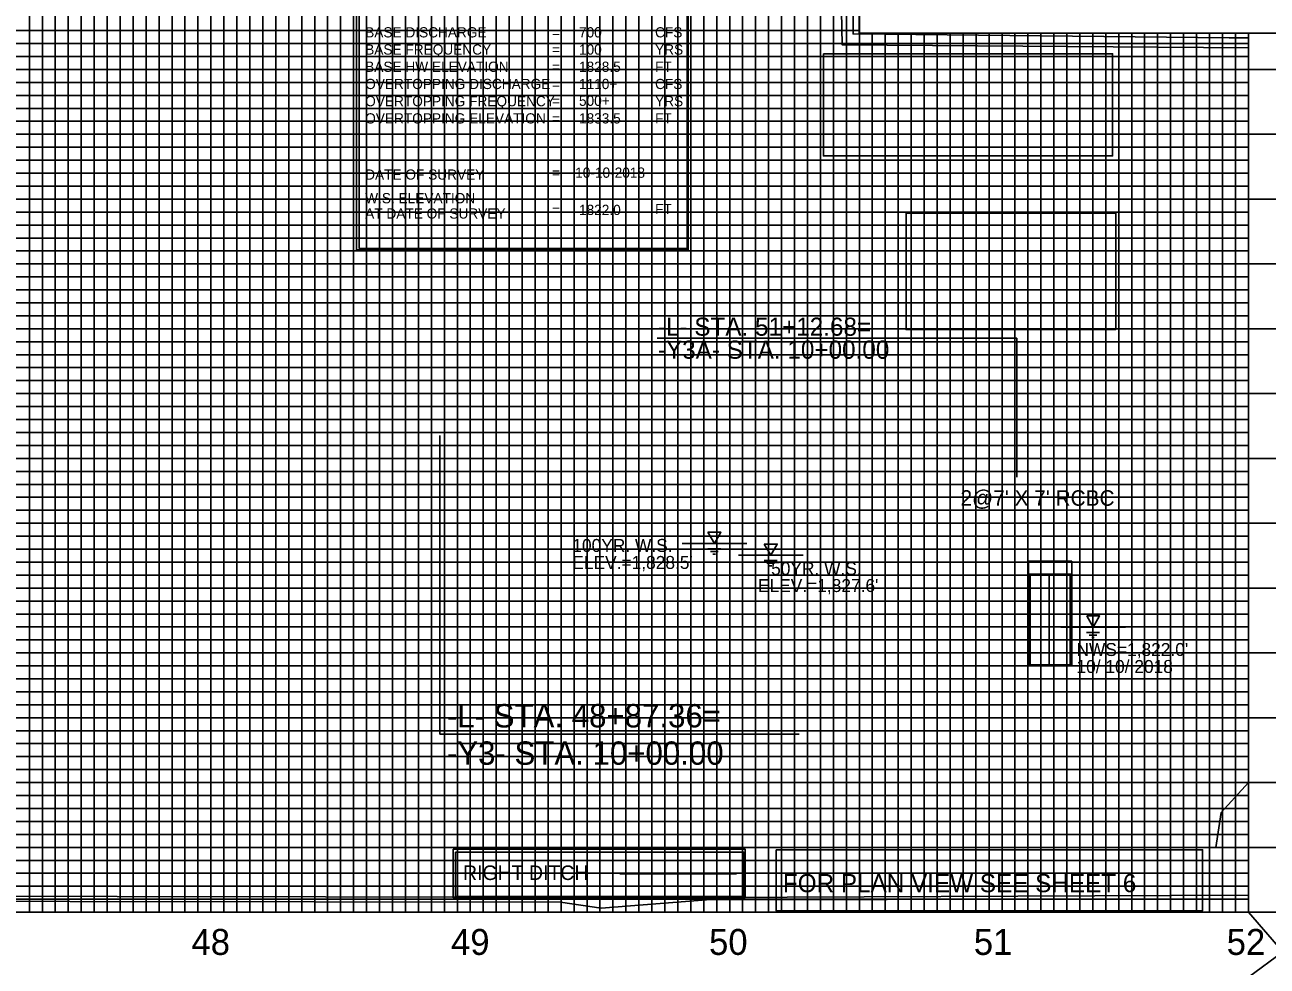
# Model space of a CAD drawing. Extents: x 557032 to 562069, y 513430 to 515874.
# Drawn here: x 558177.7 to 558656.7, y 515328.5 to 515691.5 of the extents above; entities that cross this region are included whole.
import ezdxf

# ---------------------------------------------------------------- set-up
doc = ezdxf.new("R2010")
doc.units = 0
for name, color, linetype in [('Default', 7, 'Continuous'), ('Exist Vertical Profile Horizontal Axis Label Major', 7, 'Continuous'), ('Prop Grid Mask', 7, 'Continuous'), ('Prop PFL Ditch Label CELL', 7, 'Continuous'), ('Prop Vertical Profile Curve Label', 7, 'Continuous'), ('Prop VPI Label', 7, 'Continuous'), ('Scratch_Level_5', 7, 'Continuous'), ('Sheet DOT Grid CELL', 7, 'Continuous'), ('Sheet Layout Profile Border Port 1', 7, 'Continuous'), ('Sheet Profile CELL', 7, 'Continuous'), ('Sheet Profile Grid Major CELL', 7, 'Continuous'), ('Sheet Profile Grid Middle CELL', 7, 'Continuous'), ('Sheet Profile Grid Minor CELL', 7, 'Continuous'), ('Sheet Sticker Exception Certification CELL', 7, 'Continuous')]:
    doc.layers.add(name, color=color, linetype=linetype)

msp = doc.modelspace()

# ---------------------------------------------------------------- linework, layer by layer
at = {"layer": 'Default'}
for p, q in [((558431.08, 515491.43), (558456.08, 515491.44)), ((558441, 515489.41), (558446, 515489.42)), ((558442, 515488.41), (558445, 515488.42)), ((558443, 515487.41), (558444, 515487.42)), ((558452.81, 515486.92), (558477.81, 515486.93)), ((558462.74, 515484.9), (558467.74, 515484.9)), ((558463.74, 515483.9), (558466.74, 515483.9)), ((558464.74, 515482.9), (558465.74, 515482.9)), ((558581.35, 515484.7), (558564.69, 515484.7)), ((558564.69, 515444.7), (558564.69, 515484.7)), ((558581.35, 515444.7), (558581.35, 515484.7)), ((558581.35, 515479.7), (558564.69, 515479.7)), ((558565.35, 515444.7), (558565.35, 515479.7)), ((558572.69, 515479.7), (558572.69, 515444.7)), ((558580.69, 515444.7), (558580.69, 515479.7)), ((558577.09, 515459.2), (558602.09, 515459.21)), ((558587.02, 515457.17), (558592.02, 515457.18)), ((558588.02, 515456.18), (558591.02, 515456.18)), ((558589.02, 515455.18), (558590.02, 515455.18)), ((558581.35, 515444.7), (558564.69, 515444.7))]:
    msp.add_line(p, q, dxfattribs=at)
for points in [[(558441.07, 515495.78), (558446.07, 515495.78), (558443.58, 515491.44)], [(558462.81, 515491.26), (558467.81, 515491.27), (558465.31, 515486.93)], [(558587.09, 515463.54), (558592.09, 515463.54), (558589.59, 515459.2)]]:
    msp.add_lwpolyline(points, close=True, dxfattribs=at)
at = {"layer": 'Prop Grid Mask'}
msp.add_lwpolyline([(558342.89, 515373.63), (558455.39, 515373.63), (558455.39, 515354.88), (558342.89, 515354.88)], close=True, dxfattribs=at)
at = {"layer": 'Prop PFL Ditch Label CELL'}
for p, q in [((558407.05, 515364.14), (558452.05, 515364.14)), ((558342.89, 515362.38), (558342.89, 515362.38))]:
    msp.add_line(p, q, dxfattribs=at)
at = {"layer": 'Prop Vertical Profile Curve Label'}
for points in [[(558305.55, 515740.01), (558433.43, 515740.01), (558433.43, 515604.72), (558305.55, 515604.72)], [(558485.58, 515680.31), (558597.1, 515680.31), (558597.1, 515640.93), (558485.58, 515640.93)], [(558517.44, 515618.88), (558598.31, 515618.88), (558598.31, 515573.96), (558517.44, 515573.96)]]:
    msp.add_lwpolyline(points, close=True, dxfattribs=at)
at = {"layer": 'Prop VPI Label'}
for p, q in [((558560.14, 515570.72), (558421.51, 515570.72)), ((558560.14, 515570.72), (558560.14, 515517.08)), ((558337.64, 515533.16), (558337.64, 515417.88)), ((558476.28, 515417.88), (558337.64, 515417.88))]:
    msp.add_line(p, q, dxfattribs=at)
for points in [[(558306.55, 515605.27), (558433.12, 515605.27), (558433.12, 515739.03), (558306.55, 515739.03)], [(558467.36, 515373.36), (558631.78, 515373.36), (558631.78, 515349.85), (558467.36, 515349.85)], [(558467.36, 515373.36), (558631.78, 515373.36), (558631.78, 515349.85), (558467.36, 515349.85)], [(558343.72, 515372.47), (558454.87, 515372.47), (558454.87, 515355.33), (558343.72, 515355.33)]]:
    msp.add_lwpolyline(points, close=True, dxfattribs=at)
at = {"layer": 'Scratch_Level_5'}
for p, q in [((558649.42, 515355.8), (558649.42, 515686.42)), ((558649.45, 515354.48), (558649.45, 515682.57)), ((558649.45, 515374.28), (558649.45, 515399.28)), ((558649.45, 515374.28), (558649.45, 515399.28)), ((558249.45, 515349.28), (558299.45, 515349.28))]:
    msp.add_line(p, q, dxfattribs=at)
msp.add_lwpolyline([(558499.4, 515824.23), (557249.45, 515849.28), (557249.45, 515349.28), (557236.61, 515332.67), (557249.45, 515324.28), (558649.45, 515324.28), (558662.72, 515334.01), (558649.45, 515349.28), (558649.45, 515688.23), (558499.4, 515688.23)], close=True, dxfattribs=at)
for points in [[(558649.42, 515686.42), (558641.97, 515686.42), (558497.02, 515687.96), (558497.02, 515823.15), (558090.9, 515829.21), (557249.42, 515839.17)], [(558649.45, 515682.57), (558492.81, 515683.83), (558490.11, 515820.17), (558049.46, 515829.04), (557249.45, 515836.19)], [(558649.45, 515399.28), (558639, 515387.71), (558636.95, 515374.28), (558649.45, 515374.28)], [(558649.45, 515399.28), (558639, 515387.71), (558636.95, 515374.28), (558649.45, 515374.28)], [(557249.42, 515356.85), (558373.93, 515355.08), (558412.39, 515354.77), (558649.42, 515355.8)], [(557249.45, 515354.68), (558384.27, 515353.2), (558399.94, 515350.88), (558440.57, 515354.03), (558649.45, 515354.48)]]:
    msp.add_lwpolyline(points, dxfattribs=at)
at = {"layer": 'Sheet DOT Grid CELL'}
for p, q in [((558199.45, 515349.28), (558199.45, 515849.28)), ((558249.45, 515349.28), (558249.45, 515849.28)), ((558299.45, 515349.28), (558299.45, 515849.28)), ((558349.45, 515349.28), (558349.45, 515849.28)), ((558399.45, 515349.28), (558399.45, 515849.28)), ((558449.45, 515349.28), (558449.45, 515849.28)), ((558499.45, 515349.28), (558499.45, 515711.73)), ((558549.45, 515349.28), (558549.45, 515688.23)), ((558599.45, 515349.28), (558599.45, 515688.23)), ((558649.45, 515349.28), (558649.45, 515688.23)), ((558699.45, 515649.28), (557199.45, 515649.28)), ((558699.45, 515599.28), (557199.45, 515599.28)), ((558699.45, 515549.28), (557199.45, 515549.28)), ((558699.45, 515499.28), (557199.45, 515499.28)), ((558699.45, 515449.28), (557199.45, 515449.28)), ((558699.45, 515399.28), (557199.45, 515399.28))]:
    msp.add_line(p, q, dxfattribs=at)
at = {"layer": 'Sheet Layout Profile Border Port 1'}
for points in [[(557249.45, 515688.23), (557249.45, 515349.28), (558649.45, 515349.28), (558649.45, 515688.23)], [(558649.45, 515353.08), (558649.45, 515683.7)], [(558649.45, 515354.48), (558649.45, 515682.57)], [(558649.45, 515354.48), (558649.45, 515682.57)]]:
    msp.add_lwpolyline(points, dxfattribs=at)
at = {"layer": 'Sheet Profile CELL'}
msp.add_line((557199.45, 515349.28), (558699.45, 515349.28), dxfattribs=at)
at = {"layer": 'Sheet Profile Grid Major CELL'}
for points in [[(558149.45, 515349.28), (558199.45, 515349.28), (558199.45, 515849.28), (558249.45, 515849.28), (558249.45, 515349.28), (558299.45, 515349.28), (558299.45, 515849.28), (558349.45, 515849.28), (558349.45, 515349.28), (558399.45, 515349.28), (558399.45, 515849.28), (558449.45, 515849.28), (558449.45, 515349.28), (558499.45, 515349.28), (558499.45, 515849.28), (558525.75, 515849.28)], [(558649.45, 515688.23), (558649.45, 515349.28), (558699.45, 515349.28), (558699.45, 515699.28)], [(558549.45, 515688.23), (558549.45, 515349.28), (558599.45, 515349.28), (558599.45, 515349.28), (558599.45, 515688.23)], [(558699.45, 515649.28), (557199.45, 515649.28), (557199.45, 515599.28), (558699.45, 515599.28)], [(558699.45, 515549.28), (557199.45, 515549.28), (557199.45, 515499.28), (558699.45, 515499.28)], [(558699.45, 515449.28), (557199.45, 515449.28), (557199.45, 515449.28), (557199.45, 515399.28), (558699.45, 515399.28)]]:
    msp.add_lwpolyline(points, dxfattribs=at)
at = {"layer": 'Sheet Profile Grid Middle CELL'}
for points in [[(558174.45, 515349.28), (558224.45, 515349.28), (558224.45, 515849.28), (558274.45, 515849.28), (558274.45, 515349.28), (558324.45, 515349.28), (558324.45, 515849.28), (558374.45, 515849.28), (558374.45, 515349.28), (558424.45, 515349.28), (558424.45, 515849.28), (558474.45, 515849.28), (558474.45, 515349.28), (558524.45, 515349.28), (558524.45, 515688.23)], [(558524.45, 515612.08), (558524.45, 515349.28), (558574.45, 515349.28), (558574.45, 515688.23)], [(558574.45, 515612.08), (558574.45, 515349.28), (558624.45, 515349.28), (558624.45, 515688.23)], [(558699.45, 515674.28), (557199.45, 515674.28), (557199.45, 515624.28), (558524.45, 515624.28)], [(558524.45, 515624.28), (558699.45, 515624.28)], [(558699.45, 515574.28), (557199.45, 515574.28), (557199.45, 515524.28), (558699.45, 515524.28)], [(558699.45, 515474.28), (557199.45, 515474.28), (557199.45, 515424.28), (558699.45, 515424.28)], [(558699.45, 515374.28), (557199.45, 515374.28)]]:
    msp.add_lwpolyline(points, dxfattribs=at)
at = {"layer": 'Sheet Profile Grid Minor CELL'}
for p, q in [((558499.45, 515689.28), (557249.45, 515689.28)), ((557249.45, 515684.28), (558649.45, 515684.28)), ((558649.45, 515664.28), (557249.45, 515664.28)), ((557249.45, 515659.28), (558649.45, 515659.28)), ((558649.45, 515639.28), (557249.45, 515639.28)), ((557249.45, 515634.28), (558649.45, 515634.28)), ((558649.45, 515614.28), (557249.45, 515614.28)), ((557249.45, 515609.28), (558649.45, 515609.28)), ((558649.45, 515604.28), (557249.45, 515604.28)), ((557249.45, 515594.28), (558649.45, 515594.28)), ((558649.45, 515589.28), (557249.45, 515589.28)), ((557249.45, 515584.28), (558649.45, 515584.28)), ((558649.45, 515579.28), (557249.45, 515579.28)), ((557249.45, 515569.28), (558649.45, 515569.28)), ((558649.45, 515564.28), (557249.45, 515564.28)), ((557249.45, 515559.28), (558649.45, 515559.28)), ((558649.45, 515554.28), (557249.45, 515554.28)), ((557249.45, 515544.28), (558649.45, 515544.28)), ((558649.45, 515539.28), (557249.45, 515539.28)), ((557249.45, 515534.28), (558649.45, 515534.28)), ((558649.45, 515529.28), (557249.45, 515529.28)), ((557249.45, 515519.28), (558649.45, 515519.28)), ((558649.45, 515514.28), (557249.45, 515514.28)), ((557249.45, 515509.28), (558649.45, 515509.28)), ((558649.45, 515504.28), (557249.45, 515504.28)), ((557249.45, 515494.28), (558649.45, 515494.28)), ((558649.45, 515489.28), (557249.45, 515489.28)), ((557249.45, 515484.28), (558649.45, 515484.28)), ((558649.45, 515479.28), (557249.45, 515479.28)), ((557249.45, 515469.28), (558649.45, 515469.28)), ((558649.45, 515464.28), (557249.45, 515464.28)), ((558649.45, 515459.28), (557249.45, 515459.28)), ((558649.45, 515454.28), (557249.45, 515454.28)), ((557249.45, 515444.28), (558649.45, 515444.28)), ((558649.45, 515439.28), (557249.45, 515439.28)), ((557249.45, 515434.28), (558649.45, 515434.28)), ((558649.45, 515429.28), (557249.45, 515429.28)), ((557249.45, 515419.28), (558649.45, 515419.28)), ((558649.45, 515414.28), (557249.45, 515414.28)), ((557249.45, 515409.28), (558649.45, 515409.28)), ((558649.45, 515404.28), (557249.45, 515404.28)), ((557249.45, 515394.28), (558649.45, 515394.28)), ((558649.45, 515389.28), (557249.45, 515389.28)), ((557249.45, 515384.28), (558649.45, 515384.28)), ((558649.45, 515379.28), (557249.45, 515379.28)), ((557249.45, 515369.28), (558649.45, 515369.28)), ((558649.45, 515364.28), (557249.45, 515364.28)), ((557249.45, 515359.28), (558649.45, 515359.28))]:
    msp.add_line(p, q, dxfattribs=at)
for points in [[(558179.45, 515849.28), (558179.45, 515349.28), (558184.45, 515349.28), (558184.45, 515849.28)], [(558189.45, 515849.28), (558189.45, 515349.28), (558194.45, 515349.28), (558194.45, 515849.28)], [(558204.45, 515849.28), (558204.45, 515349.28), (558209.45, 515349.28), (558209.45, 515849.28)], [(558214.45, 515849.28), (558214.45, 515349.28), (558219.45, 515349.28), (558219.45, 515849.28)], [(558229.45, 515849.28), (558229.45, 515349.28), (558234.45, 515349.28), (558234.45, 515849.28)], [(558239.45, 515849.28), (558239.45, 515349.28), (558244.45, 515349.28), (558244.45, 515849.28)], [(558254.45, 515849.28), (558254.45, 515349.28), (558259.45, 515349.28), (558259.45, 515849.28)], [(558264.45, 515849.28), (558264.45, 515349.28), (558269.45, 515349.28), (558269.45, 515849.28)], [(558279.45, 515849.28), (558279.45, 515349.28), (558284.45, 515349.28), (558284.45, 515849.28)], [(558289.45, 515849.28), (558289.45, 515349.28), (558294.45, 515349.28), (558294.45, 515849.28)], [(558304.45, 515849.28), (558304.45, 515349.28), (558309.45, 515349.28), (558309.45, 515849.28)], [(558314.45, 515849.28), (558314.45, 515349.28), (558319.45, 515349.28), (558319.45, 515849.28)], [(558329.45, 515849.28), (558329.45, 515349.28), (558334.45, 515349.28), (558334.45, 515849.28)], [(558339.45, 515849.28), (558339.45, 515349.28), (558344.45, 515349.28), (558344.45, 515849.28)], [(558354.45, 515849.28), (558354.45, 515349.28), (558359.45, 515349.28), (558359.45, 515849.28)], [(558364.45, 515849.28), (558364.45, 515349.28), (558369.45, 515349.28), (558369.45, 515849.28)], [(558379.45, 515849.28), (558379.45, 515349.28), (558384.45, 515349.28), (558384.45, 515849.28)], [(558389.45, 515849.28), (558389.45, 515349.28)], [(558389.45, 515349.28), (558394.45, 515349.28), (558394.45, 515849.28)], [(558404.45, 515849.28), (558404.45, 515349.28), (558409.45, 515349.28), (558409.45, 515849.28)], [(558414.45, 515849.28), (558414.45, 515349.28), (558419.45, 515349.28), (558419.45, 515849.28)], [(558429.45, 515849.28), (558429.45, 515349.28), (558434.45, 515349.28), (558434.45, 515849.28)], [(558439.45, 515849.28), (558439.45, 515349.28), (558444.45, 515349.28), (558444.45, 515849.28)], [(558454.45, 515849.28), (558454.45, 515349.28), (558459.45, 515349.28), (558459.45, 515849.28)], [(558464.45, 515849.28), (558464.45, 515349.28), (558469.45, 515349.28), (558469.45, 515849.28)], [(558479.45, 515849.28), (558479.45, 515349.28), (558484.45, 515349.28), (558484.45, 515849.28)], [(558489.45, 515849.28), (558489.45, 515349.28), (558494.45, 515349.28), (558494.45, 515849.28)], [(558504.45, 515688.23), (558504.45, 515349.28), (558509.45, 515349.28), (558509.45, 515688.23)], [(558514.45, 515688.23), (558514.45, 515349.28), (558519.45, 515349.28), (558519.45, 515688.23)], [(558529.45, 515688.23), (558529.45, 515349.28), (558529.45, 515349.28), (558534.45, 515349.28), (558539.45, 515349.28), (558539.45, 515688.23)], [(558534.45, 515688.23), (558534.45, 515349.28)], [(558544.45, 515688.23), (558544.35, 515349.33), (558549.35, 515349.33), (558554.45, 515349.28), (558554.45, 515688.23)], [(558554.45, 515612.08), (558554.45, 515349.28), (558559.45, 515349.28), (558559.45, 515688.23)], [(558564.45, 515688.23), (558564.45, 515349.28), (558569.45, 515349.28), (558569.45, 515688.23)], [(558579.45, 515688.23), (558579.45, 515349.28), (558584.45, 515349.28), (558584.45, 515688.23)], [(558589.45, 515688.23), (558589.45, 515349.28), (558594.45, 515349.28), (558594.45, 515688.23)], [(558604.45, 515688.23), (558604.45, 515349.28), (558609.45, 515349.28), (558609.45, 515688.23)], [(558614.45, 515688.23), (558614.45, 515349.28), (558619.45, 515349.28), (558619.45, 515688.23)], [(558629.45, 515688.23), (558629.45, 515349.28), (558634.45, 515349.28), (558634.45, 515688.23)], [(558639.45, 515688.23), (558639.45, 515349.28), (558644.45, 515349.28), (558644.45, 515688.23)], [(558649.45, 515679.28), (557249.45, 515679.28), (557249.45, 515669.28), (558649.45, 515669.28)], [(558649.45, 515654.28), (557249.45, 515654.28), (557249.45, 515644.28), (558649.45, 515644.28)], [(558649.45, 515629.28), (557249.45, 515629.28), (557249.45, 515619.28), (558649.45, 515619.28)], [(558649.45, 515354.28), (557249.45, 515354.28)]]:
    msp.add_lwpolyline(points, dxfattribs=at)
at = {"layer": 'Sheet Sticker Exception Certification CELL'}
for p, q in [((558499.4, 515688.23), (558499.4, 515711.73)), ((558499.4, 515688.23), (558499.4, 515711.73)), ((558699.44, 515688.23), (558499.4, 515688.23)), ((558699.44, 515688.23), (558499.4, 515688.23))]:
    msp.add_line(p, q, dxfattribs=at)

# ---------------------------------------------------------------- texts
at = {"layer": 'Default'}
msp.add_text("2@7' X 7' RCBC", height=6, dxfattribs=at).set_placement((558538.45, 515506.02))
for s, p in [('100YR. W.S. ', (558388.78, 515488.21)), ("ELEV.=1,828.5'", (558388.78, 515481.65)), ('   50YR. W.S. ', (558459.86, 515479.3)), ("ELEV.=1,827.6'", (558460.35, 515472.75)), ("NWS=1,822.0'", (558583.15, 515448.08)), ('10/ 10/ 2018', (558583.16, 515441.53))]:
    msp.add_text(s, height=5, rotation=0.0227, dxfattribs=at).set_placement(p)
at = {"layer": 'Exist Vertical Profile Horizontal Axis Label Major'}
for s, p in [('48', (558241.93, 515332.81)), ('49', (558342.01, 515332.81)), ('50', (558441.5, 515332.81)), ('51', (558543.57, 515332.81)), ('52', (558641.07, 515332.81))]:
    msp.add_text(s, height=10, dxfattribs=at).set_placement(p)
at = {"layer": 'Prop PFL Ditch Label CELL'}
msp.add_text('RIGHT DITCH', height=5.6138, dxfattribs=at).set_placement((558346.64, 515361.7))
at = {"layer": 'Prop VPI Label'}
for s, height, p in [('BASE DISCHARGE', 3.9375, (558308.92, 515686.64)), ('=     700', 3.937, (558380.96, 515686.64)), ('CFS', 3.937, (558420.69, 515686.64)), ('BASE FREQUENCY', 3.9375, (558308.92, 515680)), ('=     100', 3.937, (558380.96, 515680)), ('YRS', 3.937, (558420.69, 515680)), ('BASE HW ELEVATION', 3.9375, (558308.92, 515673.36)), ('=     1828.5', 3.9375, (558380.96, 515673.36)), ('FT', 3.937, (558420.69, 515673.36)), ('OVERTOPPING DISCHARGE', 3.9375, (558308.92, 515666.72)), ('=     1110+', 3.9375, (558380.96, 515666.72)), ('CFS', 3.937, (558420.69, 515666.72)), ('OVERTOPPING FREQUENCY', 3.9375, (558308.92, 515660.09)), ('=     500+', 3.937, (558380.96, 515660.25)), ('YRS', 3.937, (558420.69, 515660.09)), ('OVERTOPPING ELEVATION', 3.9375, (558308.92, 515653.45)), ('=     1833.5', 3.9374, (558380.96, 515653.45)), ('FT', 3.937, (558420.69, 515653.45)), ('=    10-10-2018', 3.9375, (558380.96, 515632.52)), ('DATE OF SURVEY', 3.9375, (558308.92, 515631.79)), ('W.S. ELEVATION', 3.9375, (558308.92, 515622.68)), ('=     1822.0', 3.9375, (558380.96, 515618.15)), ('FT', 3.937, (558420.69, 515618.49)), ('AT DATE OF SURVEY', 3.9375, (558308.92, 515616.77)), ('-L- STA. 48+87.36=', 9, (558340.41, 515420.54)), ('-Y3- STA. 10+00.00', 9, (558340.41, 515406.14)), ('FOR PLAN VIEW SEE SHEET 6', 7, (558469.96, 515356.99))]:
    msp.add_text(s, height=height, dxfattribs=at).set_placement(p)
for s, p in [('-L- STA. 51+12.68=', (558421.77, 515571.59)), ('-Y3A- STA. 10+00.00', (558421.77, 515562.72))]:
    msp.add_text(s, height=7, rotation=360, dxfattribs=at).set_placement(p)

doc.saveas('drawing.dxf')
